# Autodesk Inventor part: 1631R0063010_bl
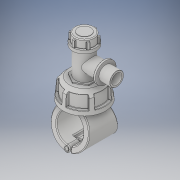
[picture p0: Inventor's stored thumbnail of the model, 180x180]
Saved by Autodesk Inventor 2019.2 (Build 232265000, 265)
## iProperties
Created: 2022-02
Part Number: 1631R0063010_bl
Material: Generic
Description: Plassadle Tapper Male 63x1''
Document SubType Name: Modeling
Designer: comp2
Density: 1 g/cm^3
Appearance: Default
Author: comp2
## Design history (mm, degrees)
derived "1631R.ipt"
feature "Solid1::1631R.ipt" dims "ScaleForDerivedMember" = 10
feature "Solid2::1631R.ipt" dims "ScaleForDerivedMember" = 10
feature "Solid3::1631R.ipt" dims "ScaleForDerivedMember" = 10
feature "Solid4::1631R.ipt" dims "ScaleForDerivedMember" = 10
tag "TaggingFeature1"
body "Solid1"
body "Solid2"
body "Solid3"
body "Solid4"
other parameters: "d" = 63 [user parameter], "d1" = 25 [user parameter], "B" = 91 [user parameter], "L" = 89 [user parameter], "E_" = 54 [user parameter], "E1" = 102 [user parameter], "H1" = 231 [user parameter], "H2" = 144 [user parameter], "H3" = 78 [user parameter], "H_costum" = 49 [user parameter], "R" = 33.249 [user parameter], "d0" = 63 [user parameter], "d2" = 91 [user parameter], "d3" = 31.5 [user parameter], "d5" = 231 [user parameter], "d7" = 86.45 [user parameter], "d8" = 85 deg [user parameter], "d9" = 45 deg [user parameter], "d10" = 102 [user parameter], "d11" = 49 [user parameter], "d12" = 34.3 [user parameter], "d13" = 42.84 [user parameter], "d14" = 57.936 [user parameter], "d15" = 2.45 [user parameter], "d16" = 2 [user parameter], "d17" = 2 [user parameter], "d18" = 29.4 [user parameter], "d19" = 7.35 [user parameter], "d20" = 1 [user parameter], "d21" = 30.6 [user parameter], "d22" = 1 [user parameter], "d23" = 14.7 [user parameter], "d24" = 78 [user parameter], "d27" = 144 [user parameter], "d29" = 49.8735 [user parameter], "d31" = 33.249 [user parameter], "d32" = 31.2 [user parameter], "d33" = 26.52 [user parameter], "d41" = 5 [user parameter], "d42" = 2.8 [user parameter], "d46" = 56.1 [user parameter], "d47" = 36.5739 [user parameter], "d48" = 49 [user parameter], "d49" = 1.82 [user parameter], "d50" = 89 [user parameter], "d51" = 0 [user parameter], "d52" = 19.6 [user parameter], "d53" = 50.05 [user parameter], "d54" = 31.15 [user parameter], "d55" = 0 [user parameter], "d56" = 17.8 [user parameter], "d57" = 17.8 [user parameter], "d59" = 0 [user parameter], "d60" = 89 [user parameter], "d61" = 0 [user parameter], "d62" = 31.15 [user parameter], "d63" = 0 [user parameter], "d65" = 0 [user parameter], "d67" = 0 [user parameter], "d69" = 0 [user parameter], "d70" = 1 [user parameter], "d71" = 85.44 [user parameter], "d72" = 0 [user parameter], "d73" = 2 [user parameter], "d77" = 24.93675 [user parameter], "d78" = 86.7 [user parameter], "d79" = 5.1 [user parameter], "d80" = 60 deg [user parameter], "d81" = 5.1 [user parameter], "d84" = 0 [user parameter], "d85" = 1 [user parameter], "d87" = 360 deg [user parameter], "d90" = 0 [user parameter], "d91" = 1 [user parameter], "d93" = 60 deg [user parameter], "d94" = 3.06 [user parameter], "d95" = 3.06 [user parameter], "d97" = 0 [user parameter], "d98" = 0.5 [user parameter], "d100" = 360 deg [user parameter], "d102" = 2 [user parameter], "d117" = 0.5 [user parameter], "d118" = 31.2 [user parameter], "d119" = 100 deg [user parameter], "d121" = 0 [user parameter]
